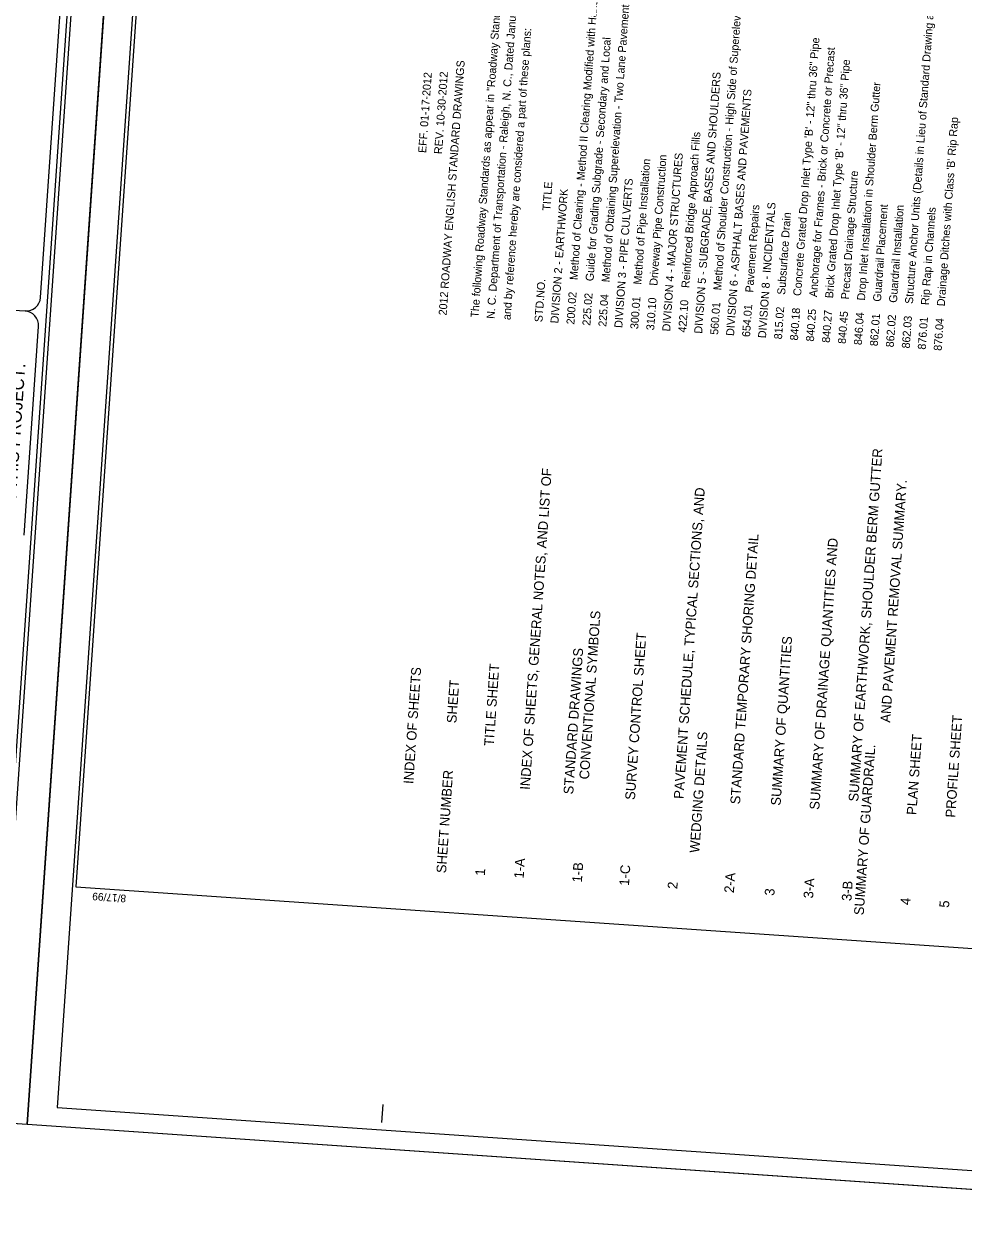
# Model space of a CAD drawing. Extents: x 2598107 to 2605763, y 726018 to 731166.
# Drawn here: x 2600571 to 2602035, y 727047 to 728931 of the extents above; entities that cross this region are included whole.
import ezdxf

# ---------------------------------------------------------------- set-up
doc = ezdxf.new("R2010")
doc.units = 0
for name, color, linetype in [('Old_Level_38', 7, 'Continuous'), ('Prop EOT', 7, 'Continuous'), ('Sheet Cutting Line CELL', 7, 'Continuous'), ('Sheet Plan CELL', 7, 'Continuous'), ('Sheet Plot Border Inside CELL', 7, 'Continuous'), ('Sheet Plot Border Outside CELL', 7, 'Continuous'), ('Sheet Title CELL', 7, 'Continuous')]:
    doc.layers.add(name, color=color, linetype=linetype)

msp = doc.modelspace()

# ---------------------------------------------------------------- linework, layer by layer
at = {"layer": 'Sheet Cutting Line CELL'}
for p, q in [((2600575.7, 727216), (2600836, 730996)), ((2600836, 730994.9), (2600575.7, 727216)), ((2598106.6, 727386), (2600575.7, 727216)), ((2600575.7, 727216), (2603033.6, 727046.7))]:
    msp.add_line(p, q, dxfattribs=at)
at = {"layer": 'Sheet Plan CELL'}
for p, q in [((2600651.9, 727586.2), (2600651.9, 727586.2)), ((2601128.4, 727218.5), (2601130.4, 727246.6))]:
    msp.add_line(p, q, dxfattribs=at)
msp.add_lwpolyline([(2600883.8, 730953.3), (2600651.9, 727586.2), (2603008.9, 727423.9), (2603240.7, 730790.9)], close=True, dxfattribs=at)
at = {"layer": 'Sheet Plot Border Inside CELL'}
for points in [[(2600527.3, 727248.6), (2600785, 730989.4), (2598416.6, 731152.5), (2598159, 727411.7)], [(2602990.7, 727079), (2603248.3, 730818.6), (2600880.2, 730981.7), (2600622.6, 727242.1)]]:
    msp.add_lwpolyline(points, close=True, dxfattribs=at)
at = {"layer": 'Sheet Plot Border Outside CELL'}
for points in [[(2598366.9, 731166.1), (2598106.6, 727386), (2600575.7, 727216), (2600836, 730996)], [(2603033.6, 727046.7), (2603293.9, 730825.6), (2600836, 730994.9), (2600575.7, 727216)]]:
    msp.add_lwpolyline(points, close=True, dxfattribs=at)
at = {"layer": 'Sheet Title CELL'}
msp.add_line((2600213.6, 728508.4), (2600572.8, 728483.7), dxfattribs=at)
for points in [[(2600547, 727617.2), (2600775.8, 730939.3)], [(2600596.8, 728504.6), (2600655.6, 729357.6)], [(2600571.3, 728134.2), (2600593.7, 728459.7)]]:
    msp.add_lwpolyline(points, dxfattribs=at)
for centre, start, end in [((2600574.2, 728506.1), 266.0601, 356.0601), ((2600571.1, 728461.2), 356.0601, 86.0601)]:
    msp.add_arc(centre, 22.5, start, end, dxfattribs=at)

# ---------------------------------------------------------------- texts
at = {"layer": 'Old_Level_38'}
msp.add_text('ON THIS PROJECT.', height=19.688, rotation=86.0601, dxfattribs=at).set_placement((2600556.4, 728157.9))
at = {"layer": 'Prop EOT'}
for s, height, rotation, p in [('The following Roadway Standards as appear in "Roadway Standard Drawings" Highway Design Branch -', 12.474, 85.9164, (2601279.2, 728472.9)), ('N. C. Department of Transportation - Raleigh, N. C., Dated January, 2012 are applicable to this project', 12.474, 85.9164, (2601304.1, 728471.1)), ("200.02    Method of Clearing - Method II Clearing Modified with Hand Claering 3' beyond toe of slope.", 12.474, 85.9164, (2601428.5, 728462.2)), ('560.01    Method of Shoulder Construction - High Side of Superelevated Curve - Method I', 12.474, 85.9164, (2601652.5, 728446.2)), ('862.03    Structure Anchor Units (Details in Lieu of Standard Drawing as March 2013 Letting)', 12.474, 85.9164, (2601951.1, 728424.9)), ('225.04    Method of Obtaining Superelevation - Two Lane Pavement', 12.474, 85.9164, (2601478.3, 728458.7)), ('and by reference hereby are considered a part of these plans:', 12.474, 85.9164, (2601329, 728469.3)), ('225.02    Guide for Grading Subgrade - Secondary and Local', 12.474, 85.9164, (2601453.4, 728460.4)), ('840.18    Concrete Grated Drop Inlet Type \'B\' - 12" thru 36" Pipe', 12.474, 85.9164, (2601776.9, 728437.3)), ('840.25    Anchorage for Frames - Brick or Concrete or Precast', 12.474, 85.9164, (2601801.8, 728435.6)), ('2012 ROADWAY ENGLISH STANDARD DRAWINGS', 12.474, 85.9164, (2601229.4, 728476.4)), ('840.27    Brick Grated Drop Inlet Type \'B\' - 12" thru 36" Pipe', 12.474, 85.9164, (2601826.7, 728433.8)), ('                                                      EFF. 01-17-2012', 12.474, 85.9164, (2601179.7, 728480)), ('                                                      REV. 10-30-2012', 12.474, 85.9164, (2601204.5, 728478.2)), ('DIVISION 5 - SUBGRADE, BASES AND SHOULDERS', 12.474, 85.9164, (2601627.6, 728448)), ('DIVISION 6 - ASPHALT BASES AND PAVEMENTS', 12.474, 85.9164, (2601677.3, 728444.4)), ('846.04    Drop Inlet Installation in Shoulder Berm Gutter', 12.474, 85.9164, (2601876.4, 728430.2)), ("876.04    Drainage Ditches with Class 'B' Rip Rap", 12.474, 85.9164, (2602000.8, 728421.3)), ('422.10    Reinforced Bridge Approach Fills', 12.474, 85.9164, (2601602.7, 728449.8)), ('300.01    Method of Pipe Installation ', 12.474, 85.9164, (2601528, 728455.1)), ('310.10    Driveway Pipe Construction', 12.474, 85.9164, (2601552.9, 728453.3)), ('DIVISION 4 - MAJOR STRUCTURES', 12.474, 85.9164, (2601577.8, 728451.5)), ('840.45    Precast Drainage Structure', 12.474, 85.9164, (2601851.5, 728432)), ('STD.NO.                       TITLE', 12.474, 85.9164, (2601378.7, 728465.8)), ('DIVISION 3 - PIPE CULVERTS', 12.474, 85.9164, (2601503.2, 728456.9)), ('DIVISION 2 - EARTHWORK', 12.474, 85.9164, (2601403.6, 728464)), ('654.01    Pavement Repairs', 12.474, 85.9164, (2601702.2, 728442.7)), ('DIVISION 8 - INCIDENTALS', 12.474, 85.9164, (2601727.1, 728440.9)), ('862.01    Guardrail Placement', 12.474, 85.9164, (2601901.3, 728428.4)), ('862.02    Guardrail Installation', 12.474, 85.9164, (2601926.2, 728426.7)), ('876.01    Rip Rap in Channels', 12.474, 85.9164, (2601976, 728423.1)), ('815.02    Subsurface Drain', 12.474, 85.9164, (2601752, 728439.1)), ('3-B                      SUMMARY OF EARTHWORK, SHOULDER BERM GUTTER ', 15.156, 86.0601, (2601860.2, 727563.5)), ('1-A                   INDEX OF SHEETS, GENERAL NOTES, AND LIST OF ', 15.156, 86.0601, (2601349.5, 727598.7)), ('2                       PAVEMENT SCHEDULE, TYPICAL SECTIONS, AND ', 15.156, 86.0601, (2601588.9, 727582.2)), ('AND PAVEMENT REMOVAL SUMMARY.', 15.156, 86.0601, (2601920.6, 727841.7)), ('2-A                   STANDARD TEMPORARY SHORING DETAIL', 15.156, 86.0601, (2601677.1, 727576.1)), ('3-A                   SUMMARY OF DRAINAGE QUANTITIES AND', 15.156, 86.0601, (2601800.6, 727567.6)), ('1-B                       CONVENTIONAL SYMBOLS ', 15.156, 86.0601, (2601440.2, 727592.4)), ('1-C                  SURVEY CONTROL SHEET', 15.156, 86.0601, (2601513.6, 727587.4)), ('3                       SUMMARY OF QUANTITIES ', 15.156, 86.0601, (2601740.1, 727571.8)), ('                        STANDARD DRAWINGS', 15.156, 86.0601, (2601417.4, 727595)), ('                        INDEX OF SHEETS ', 15.156, 86.0601, (2601168.1, 727611.2)), ('1                                  TITLE SHEET', 15.156, 86.0601, (2601289, 727602.9)), ('SHEET NUMBER             SHEET   ', 15.156, 86.0601, (2601228.6, 727607)), ('5                       PROFILE SHEET  ', 15.156, 86.0601, (2602012.3, 727553.1)), ('                        WEDGING DETAILS ', 15.156, 86.0601, (2601613.9, 727503.8)), ('4                       PLAN SHEET', 15.156, 86.0601, (2601951.8, 727557.2)), ('                                SUMMARY OF GUARDRAIL. ', 15.156, 86.0601, (2601867, 727361.6))]:
    msp.add_text(s, height=height, rotation=rotation, dxfattribs=at).set_placement(p)
at = {"layer": 'Sheet Plan CELL'}
msp.add_text('8/17/99', height=11.81, rotation=176.0601, dxfattribs=at).set_placement((2600730.4, 727573.5))

doc.saveas('drawing.dxf')
